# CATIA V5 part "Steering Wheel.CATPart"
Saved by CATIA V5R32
Part number: Steering Wheel
Bounding box of the stored display mesh (mm): x -360.883 to 360.883, y -360.883 to 360.883, z 0 to 350
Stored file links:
  D:\PROJECTS\Project 2022\CATIA V5 6R 2022\Resources\Part Files\c16_catia_v5_6r2022_prt\Revolute Joint-(Fig 16-3)\Steering Wheel.CATPart
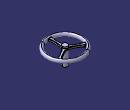
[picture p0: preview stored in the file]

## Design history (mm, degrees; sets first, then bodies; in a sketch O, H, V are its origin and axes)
Body1 (main body)
  Sketch1 on xy-plane, origin (0, 0, 0), H (1, 0, 0), V (0, 1, 0)
    circle A1 centre (0, 0) radius 50
    radius A1 = 50
  Pad1: profile Sketch1, direction (0, 0, 1), length 350
  Plane1: type Offset, RefPlane end face of Pad1, Offset 50
  Sketch2 on Plane1, origin (0, 0, 300), H (1, 0, 0), V (0, -1, 0)
    arc A1 centre (-620.9475, 180) radius 600 from (-40, 30) to (-40, 330) ccw
    point P1 (-620.9475, 180)
    point P2 (-40, 30)
    point P3 (-40, 330)
    reference projected circle E1 centre (0, 0) radius 50 from edge [start face of Pad1 | face of Pad1 from Sketch1.A1]
    construction line L1 (-40, 30) -> (-40, 330)
    point P4 (40, 330)
    point P5 (40, 30)
    arc A2 centre (620.9475, 180) radius 600 from (40, 30) to (40, 330) cw
    line L2 (-40, 30) -> (40, 30)
    line L3 (-40, 330) -> (40, 330)
    radius A1 = 600
    length L1 = 300
    distance H P1 = 180
    coincidence: P2 E1
    vertical: L1 V
    symmetry: P3 P4 V, P2 P5 V, A1 A2 V
    horizontal: L2 H, L3 H
  Pad2: profile Sketch2, direction (0, 0, -1), length 20, mirrored extent
  Fillet1: radius 7, on edge [start face of Pad2 | face of Pad2 from Sketch2.A1]; edge [face of Pad2 from Sketch2.A1 | end face of Pad2]; edge [face of Pad2 from Sketch2.A2 | end face of Pad2]; edge [start face of Pad2 | face of Pad2 from Sketch2.A2]; edge [face of Pad2 from Sketch2.A2 | face of Pad1 from Sketch1.A1]; edge [end face of Pad2 | face of Pad1 from Sketch1.A1]; edge [face of Pad1 from Sketch1.A1 | face of Pad2 from Sketch2.A1]; edge [face of Pad1 from Sketch1.A1 | start face of Pad2]
  CircPattern1: of Pad2, instances 3, angular step 120 {= 360.0*1 deg/CircPattern1.AngularNumber}, axis from face of Pad1 from Sketch1.A1
  Fillet2: radius 7, on edge [face of CircPattern1 | face of CircPattern1] (x2); face of CircPattern1 (x10)
  Sketch3 on yz-plane, origin (0, 0, 0), H (0, 1, 0), V (0, 0, 1)
    point P1 (-330, 300)
    ellipse A1 centre (-330, 300) semi-axes 37.5, 30.9839 rotation 90
    reference projected line E1 (-330, 320) -> (-330, 280) from edge [face of Pad2 from Sketch2.L3 | face of Pad2 from Sketch2.A2]
    reference projected line E2 (-49.5784, 320) -> (-330, 320) from edge [start face of Pad2 | face of Fillet1]
    distance P1 E2 = 20
    "Radius" A1 = 37.5
    coincidence: P1 E1
  Shaft1: profile Sketch3, axis axis of face of Pad1 from Sketch1.A1, angle 360
  Fillet3: radius 7, on face of Shaft1 from Sketch3.A1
